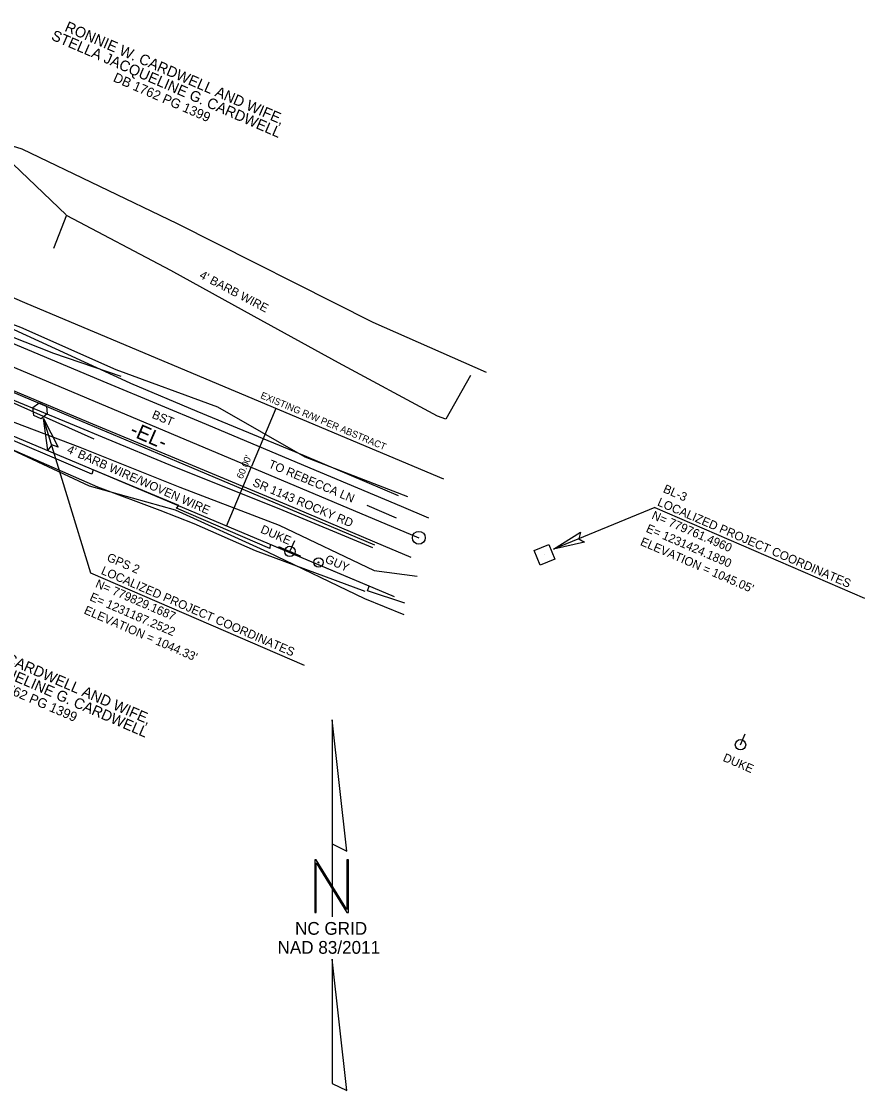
# Model space of a CAD drawing. Extents: x 1230592 to 1231575, y 779497 to 780221.
# Drawn here: x 1231178 to 1231575, y 779510 to 780012 of the extents above; entities that cross this region are included whole.
import ezdxf

# ---------------------------------------------------------------- set-up
doc = ezdxf.new("R2010")
doc.units = 0
for name, color, linetype in [('CTL GPS Vertical CELL', 7, 'Continuous'), ('CTL North Arrow NAD 83 2001 CELL', 7, 'Continuous'), ('CTL Supplemental Horizontal and Vertical CELL', 7, 'Continuous'), ('CTL Supplemental Horizontal and Vertical Text', 7, 'Continuous'), ('Default', 7, 'Continuous'), ('Exist Guardrail', 7, 'Continuous'), ('Exist Horizontal Alignment', 7, 'Continuous'), ('Exist Horizontal Alignment Direction Label', 7, 'Continuous'), ('Exist Horizontal Alignment Point', 7, 'Continuous'), ('Exist Other Culture Anchor (Guy Wire) CELL', 7, 'Continuous'), ('Exist Other Culture Anchor (Guy Wire) Text', 7, 'Continuous'), ('Exist Other Culture Fence Line', 7, 'Continuous'), ('Exist Other Culture Fence Line Text', 7, 'Continuous'), ('Exist Property Deed Book Text', 7, 'Continuous'), ('Exist Property Owner Text', 7, 'Continuous'), ('Exist Right of Way Line', 7, 'Continuous'), ('Exist Right of Way Line Text', 7, 'Continuous'), ('Exist Right of Way Width CELL', 7, 'Continuous'), ('Exist Roads EOP', 7, 'Continuous'), ('Exist Roads EOP Leader', 7, 'Continuous'), ('Exist Roads EOP Text', 7, 'Continuous'), ('Exist Utilities Power Joint Use Telephone CELL', 7, 'Continuous'), ('Exist Utilities Power Pole CELL', 7, 'Continuous'), ('Exist Utilities Power Pole Text', 7, 'Continuous'), ('Exist Utilities Sanitary Sewer Forced Main SUE', 7, 'Continuous'), ('Exist Utilities Telephone UG Cable SUE', 7, 'Continuous'), ('Exist Utilities Telephone UG FO SUE', 7, 'Continuous'), ('Exist Utilities Water UG Line SUE', 7, 'Continuous'), ('Exist Vegetation Woods Line', 7, 'Continuous'), ('Old_Level_11', 7, 'Continuous')]:
    doc.layers.add(name, color=color, linetype=linetype)

msp = doc.modelspace()

# ---------------------------------------------------------------- linework, layer by layer
at = {"layer": 'CTL GPS Vertical CELL'}
msp.add_line((1231187.25, 779829.17), (1231187.25, 779829.17), dxfattribs=at)
msp.add_lwpolyline([(1231190.25, 779831.39), (1231190.63, 779827.69), (1231187.7, 779825.42), (1231184.3, 779826.94), (1231183.85, 779830.67), (1231186.79, 779832.89)], close=True, dxfattribs=at)
at = {"layer": 'CTL North Arrow NAD 83 2001 CELL'}
msp.add_line((1231324.67, 779596.63), (1231324.67, 779596.63), dxfattribs=at)
for points in [[(1231324.52, 779683.92), (1231324.52, 779625.6), (1231331.39, 779622.16)], [(1231316.29, 779593.37), (1231316.98, 779593.37), (1231316.98, 779616.7), (1231331.39, 779593.37), (1231332.08, 779593.37), (1231332.08, 779618.06), (1231331.39, 779618.06), (1231331.39, 779594.73), (1231316.98, 779618.06), (1231316.29, 779618.06)], [(1231324.52, 779513.08), (1231331.39, 779509.67), (1231324.52, 779571.41)]]:
    msp.add_lwpolyline(points, close=True, dxfattribs=at)
msp.add_lwpolyline([(1231324.52, 779625.6), (1231324.52, 779591.3)], dxfattribs=at)
at = {"layer": 'CTL Supplemental Horizontal and Vertical CELL'}
msp.add_line((1231424.19, 779761.5), (1231424.19, 779761.5), dxfattribs=at)
msp.add_lwpolyline([(1231419.39, 779763.54), (1231426.26, 779766.33), (1231429.05, 779759.45), (1231422.19, 779756.66)], close=True, dxfattribs=at)
at = {"layer": 'Default'}
for p, q in [((1231211.15, 779752.89), (1231188.9, 779825.49)), ((1231476.14, 779783.77), (1231428.4, 779764.1)), ((1231476.14, 779783.77), (1231574.65, 779741.11)), ((1231311.43, 779709.45), (1231211.15, 779752.89))]:
    msp.add_line(p, q, dxfattribs=at)
at = {"layer": 'Exist Guardrail'}
for points in [[(1231094.67, 779896.56), (1231106.57, 779891.25), (1231147.08, 779874.58), (1231193.52, 779856.23), (1231225.11, 779845.42)], [(1231212.59, 779815.83), (1231170.99, 779834.49), (1231142.36, 779847.53), (1231097.81, 779869.64), (1231085.25, 779875.1)]]:
    msp.add_lwpolyline(points, dxfattribs=at)
at = {"layer": 'Exist Horizontal Alignment'}
msp.add_line((1231169.29, 779851.95), (1231365.2, 779769.48), dxfattribs=at)
at = {"layer": 'Exist Horizontal Alignment Point'}
msp.add_circle((1231365.2, 779769.48), 3, dxfattribs=at)
at = {"layer": 'Exist Other Culture Anchor (Guy Wire) CELL'}
for radius in [2.18, 0.24]:
    msp.add_circle((1231318.07, 779757.9), radius, dxfattribs=at)
at = {"layer": 'Exist Other Culture Fence Line'}
msp.add_line((1231199.66, 779921.06), (1231193.53, 779905.4), dxfattribs=at)
for points in [[(1231106.62, 779905.44), (1231097.65, 779911.94), (1231115.71, 779948.7), (1231133.36, 779983.07), (1231163.63, 779955.4), (1231199.43, 779921.3)], [(1231389.51, 779845.68), (1231377.81, 779825.21), (1231373.98, 779826.62), (1231327.47, 779851.69), (1231287.76, 779873.49), (1231248.59, 779895.08), (1231200, 779920.75)], [(1231358.68, 779738.78), (1231341.04, 779744.62), (1231341.83, 779746.77), (1231295.34, 779766.3), (1231295.25, 779764.41), (1231251.39, 779783.37), (1231252.48, 779784.6), (1231212.18, 779801.44), (1231211.6, 779799.44), (1231160.12, 779821.33), (1231160.3, 779822.9), (1231132.87, 779834.86)]]:
    msp.add_lwpolyline(points, dxfattribs=at)
at = {"layer": 'Exist Right of Way Line'}
for p, q in [((1230997.11, 779958.14), (1231181, 779879.57)), ((1231181, 779879.57), (1231376.84, 779797.13)), ((1231157.58, 779824.33), (1231353.56, 779741.83))]:
    msp.add_line(p, q, dxfattribs=at)
at = {"layer": 'Exist Right of Way Width CELL'}
for p in [(1231298.03, 779830.3), (1231274.75, 779775)]:
    msp.add_line(p, (1231286.51, 779802.93), dxfattribs=at)
at = {"layer": 'Exist Roads EOP'}
for points in [[(1231369.95, 779778.67), (1231357.05, 779784.21), (1231311.13, 779803.5), (1231265.43, 779822.7), (1231218.7, 779842.17), (1231173.63, 779861.08), (1231127.32, 779880.41), (1231096.67, 779893.88), (1231094.02, 779896.68)], [(1231361.52, 779760.15), (1231348.64, 779765.72), (1231303.18, 779784.92), (1231256.96, 779804.19), (1231211.97, 779822.95), (1231165.7, 779842.33), (1231119.41, 779861.89), (1231087.68, 779875.13), (1231085.4, 779874.13)]]:
    msp.add_lwpolyline(points, dxfattribs=at)
at = {"layer": 'Exist Roads EOP Leader'}
msp.add_lwpolyline([(1231354.69, 779778.74), (1231340.95, 779784.61)], dxfattribs=at)
at = {"layer": 'Exist Utilities Power Joint Use Telephone CELL'}
msp.add_line((1231304.64, 779763.07), (1231304.64, 779763.07), dxfattribs=at)
msp.add_lwpolyline([(1231299.21, 779765.46), (1231309.57, 779760.86), (1231304.63, 779763.05), (1231306.91, 779768.22)], dxfattribs=at)
msp.add_circle((1231304.64, 779763.07), 2.45, dxfattribs=at)
at = {"layer": 'Exist Utilities Power Pole CELL'}
for q in [(1231518.6, 779677.38), (1231516.33, 779672.23)]:
    msp.add_line((1231516.33, 779672.23), q, dxfattribs=at)
msp.add_circle((1231516.33, 779672.23), 2.45, dxfattribs=at)
at = {"layer": 'Exist Utilities Sanitary Sewer Forced Main SUE'}
for points in [[(1231147.57, 779820.67), (1231173.88, 779811.16), (1231214.21, 779793.43), (1231243.53, 779782.39), (1231259.44, 779776.13)], [(1231259.44, 779776.13), (1231288.25, 779763.46), (1231339.78, 779744.32)]]:
    msp.add_lwpolyline(points, dxfattribs=at)
at = {"layer": 'Exist Utilities Telephone UG Cable SUE'}
msp.add_lwpolyline([(1231100.21, 779850.34), (1231103.62, 779851.47), (1231157.91, 779840.98), (1231205.88, 779821.28), (1231216.34, 779816.85), (1231250.37, 779802.85), (1231299.48, 779783.28), (1231343.46, 779764.91)], dxfattribs=at)
at = {"layer": 'Exist Utilities Telephone UG FO SUE'}
msp.add_lwpolyline([(1231100.21, 779850.34), (1231099.62, 779852.08), (1231101.93, 779854.69), (1231110.33, 779859.1), (1231159.29, 779844.31), (1231206.7, 779824.23), (1231251.36, 779805.47), (1231300.71, 779784.68), (1231344.32, 779766.23)], dxfattribs=at)
at = {"layer": 'Exist Utilities Water UG Line SUE'}
for points in [[(1230978.2, 779957.72), (1231227.32, 779843.3)], [(1231227.32, 779843.3), (1231229.65, 779842.09), (1231260.84, 779828.97), (1231311.27, 779808.17), (1231355.54, 779789.35)]]:
    msp.add_lwpolyline(points, dxfattribs=at)
at = {"layer": 'Exist Vegetation Woods Line'}
for points in [[(1231107.46, 779927.68), (1231126.97, 779968.29), (1231178.61, 779952.25), (1231251.71, 779917.22), (1231343.53, 779870.76), (1231396.84, 779847.32)], [(1231360.02, 779788.69), (1231311.8, 779807.41), (1231270.82, 779830.89), (1231223.04, 779848.46), (1231178.15, 779868.3), (1231134.8, 779884.54), (1231105.56, 779897.88)], [(1231107.48, 779851.91), (1231158.34, 779830.07), (1231205.95, 779812.14), (1231252.83, 779793.24), (1231299.52, 779775.45), (1231344.24, 779754.18), (1231364.39, 779751.49)], [(1231358.3, 779733.3), (1231339.79, 779740.73), (1231294.17, 779762.77), (1231250.9, 779782.46), (1231210.44, 779793.71), (1231159.47, 779817.51), (1231119.25, 779834.39), (1231095.28, 779830.4)]]:
    msp.add_lwpolyline(points, dxfattribs=at)
at = {"layer": 'Old_Level_11'}
for points in [[(1231190.8, 779810.64), (1231188.9, 779825.49), (1231195.75, 779812.08), (1231192.7, 779813.11)], [(1231443, 779767.37), (1231428.4, 779764.1), (1231441.11, 779772.17), (1231440.36, 779769.03)]]:
    msp.add_lwpolyline(points, close=True, dxfattribs=at)

# ---------------------------------------------------------------- texts
at = {"layer": 'CTL North Arrow NAD 83 2001 CELL'}
for s, p in [('NC GRID', (1231307.02, 779582.91)), ('NAD 83/2011', (1231298.8, 779573.99))]:
    msp.add_text(s, height=6, rotation=360, dxfattribs=at).set_placement(p)
at = {"layer": 'CTL Supplemental Horizontal and Vertical Text'}
for s, p in [('BL-3', (1231479.63, 779791)), ('LOCALIZED PROJECT COORDINATES', (1231476.95, 779784.79)), ('N= 779761.4960', (1231474.27, 779778.59)), ('E= 1231424.1890', (1231471.59, 779772.38)), ("ELEVATION = 1045.05'", (1231468.91, 779766.18)), ('GPS 2', (1231218.24, 779758.8)), ('LOCALIZED PROJECT COORDINATES', (1231215.56, 779752.6)), ('N= 779829.1687', (1231212.88, 779746.4)), ('E= 1231187.2522', (1231210.2, 779740.19)), ("ELEVATION = 1044.33'", (1231207.52, 779733.99))]:
    msp.add_text(s, height=4.055, rotation=336.6486, dxfattribs=at).set_placement(p)
at = {"layer": 'Exist Horizontal Alignment Direction Label'}
msp.add_text('-EL-', height=7, rotation=336.5812, dxfattribs=at).set_placement((1231228.92, 779817.87))
at = {"layer": 'Exist Other Culture Anchor (Guy Wire) Text'}
msp.add_text('GUY', height=4, rotation=336.5812, dxfattribs=at).set_placement((1231320.76, 779758.01))
at = {"layer": 'Exist Other Culture Fence Line Text'}
for s, rotation, p in [("4' BARB WIRE", 332.3105, (1231261.76, 779891.73)), ("4' BARB WIRE/WOVEN WIRE", 336.2805, (1231199.52, 779809.58))]:
    msp.add_text(s, height=4, rotation=rotation, dxfattribs=at).set_placement(p)
at = {"layer": 'Exist Property Deed Book Text'}
for p in [(1231221.23, 779984.13), (1231158.63, 779702.27)]:
    msp.add_text('DB 1762 PG 1399', height=4.5, rotation=336.5812, dxfattribs=at).set_placement(p)
at = {"layer": 'Exist Property Owner Text'}
for s, p in [('RONNIE W. CARDWELL AND WIFE,', (1231198.44, 780007.8)), ('STELLA JACQUELINE G. CARDWELL', (1231192.12, 780003.71)), ('RONNIE W. CARDWELL AND WIFE,', (1231135.84, 779725.94)), ('STELLA JACQUELINE G. CARDWELL', (1231129.53, 779721.85))]:
    msp.add_text(s, height=5, rotation=336.5812, dxfattribs=at).set_placement(p)
at = {"layer": 'Exist Right of Way Line Text'}
msp.add_text('EXISTING R/W PER ABSTRACT', height=3.2, rotation=337.1715, dxfattribs=at).set_placement((1231290.5, 779835.21))
at = {"layer": 'Exist Right of Way Width CELL'}
msp.add_text("60.00'", height=3.2, rotation=67.1715, dxfattribs=at).set_placement((1231282.3, 779796.85))
at = {"layer": 'Exist Roads EOP Text'}
for s, rotation, p in [('BST', 337.3876, (1231239.46, 779825.91)), ('TO REBECCA LN', 337.0976, (1231294.22, 779802.64)), ('SR 1143 ROCKY RD', 337.0976, (1231286.75, 779794.03))]:
    msp.add_text(s, height=4, rotation=rotation, dxfattribs=at).set_placement(p)
at = {"layer": 'Exist Utilities Power Pole Text'}
for p in [(1231290.47, 779772), (1231507.75, 779664.71)]:
    msp.add_text('DUKE', height=4, rotation=336.5812, dxfattribs=at).set_placement(p)

doc.saveas('drawing.dxf')
